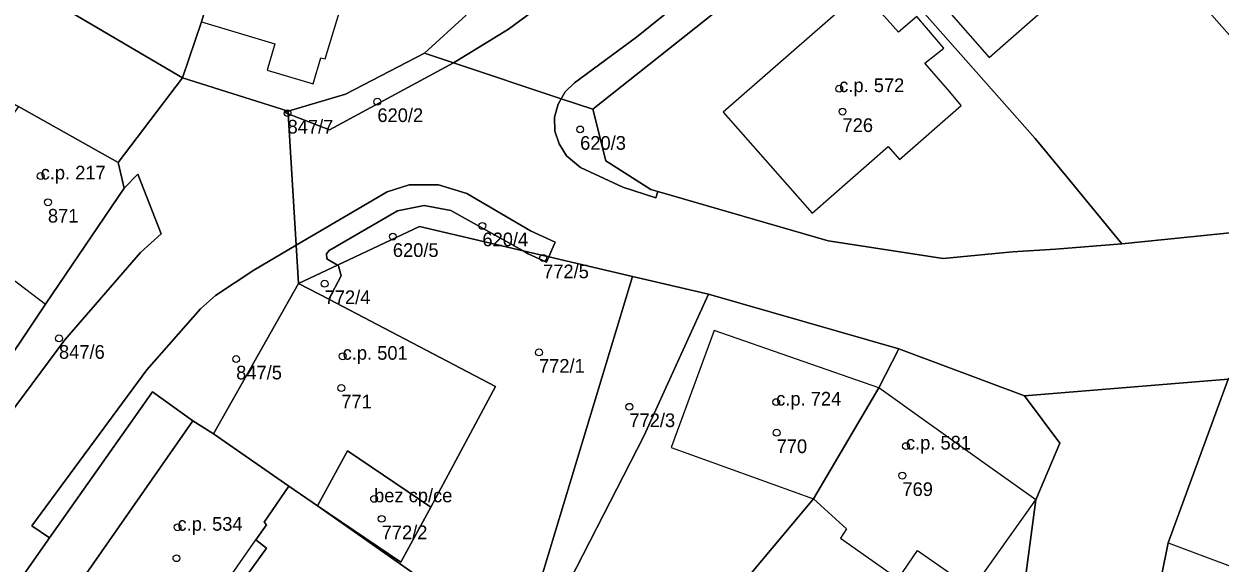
# Model space of a CAD drawing. Extents: x -878211 to -870363, y -1058464 to -1052522.
# Drawn here: x -874758 to -874670.5, y -1056517.4 to -1056478 of the extents above; entities that cross this region are included whole.
import ezdxf

# ---------------------------------------------------------------- set-up
doc = ezdxf.new("R2010")
doc.units = 0
for name, color, linetype in [('Definiční body', 7, 'Continuous'), ('Polygon budovy', 7, 'Continuous'), ('Polygon parcely', 7, 'Continuous')]:
    doc.layers.add(name, color=color, linetype=linetype)

msp = doc.modelspace()

# ---------------------------------------------------------------- linework, layer by layer
at = {"layer": 'Definiční body'}
for centre in [(-874698.4, -1056482.68994), (-874732.18, -1056483.63994), (-874698.16, -1056484.36994), (-874738.75, -1056484.47994), (-874717.35, -1056485.66994), (-874756.81, -1056489.07994), (-874756.28, -1056490.99994), (-874724.5, -1056492.72994), (-874731.05, -1056493.50994), (-874720.06, -1056495.06994), (-874736.04, -1056496.95994), (-874755.47, -1056500.95994), (-874742.51, -1056502.46994), (-874734.72, -1056502.26994), (-874720.36, -1056501.97994), (-874734.82, -1056504.58994), (-874713.75, -1056505.95994), (-874703.01, -1056505.61994), (-874702.98, -1056507.85994), (-874693.52, -1056508.83994), (-874693.78, -1056510.99994), (-874732.42, -1056512.69994), (-874731.87, -1056514.15994), (-874746.8, -1056514.77994), (-874746.88, -1056517.03994)]:
    msp.add_circle(centre, 0.25, dxfattribs=at)
at = {"layer": 'Polygon budovy'}
for points in [[(-874693.85, -1056473.06), (-874687.43, -1056480.41), (-874678.31, -1056472.38), (-874684.73, -1056465.04)], [(-874745.05, -1056477.8), (-874739.68, -1056479.4), (-874740.25, -1056481.34), (-874736.87, -1056482.34), (-874736.32, -1056480.43), (-874736.01, -1056480.5), (-874733.17, -1056471.2), (-874742.21, -1056468.41)], [(-874706.88, -1056484.4), (-874700.38, -1056491.8), (-874694.82, -1056486.91), (-874693.98, -1056487.87), (-874689.47, -1056483.92), (-874690.32, -1056482.93), (-874692.13, -1056480.82), (-874690.75, -1056479.72), (-874692.72, -1056477.42), (-874694.07, -1056478.56), (-874696.75, -1056475.52)], [(-874764.37, -1056492.43), (-874756.45, -1056498.46), (-874750.71, -1056489.97), (-874751.15, -1056488.09), (-874758.44, -1056484)], [(-874723.55, -1056504.49), (-874735.74, -1056498.1), (-874737.95, -1056496.94), (-874744.18, -1056507.93), (-874738.66, -1056511.77), (-874736.56, -1056513.22), (-874734.36, -1056509.18), (-874728.26, -1056513.3)], [(-874710.7, -1056508.95), (-874700.29, -1056512.7), (-874695.5, -1056504.57), (-874707.54, -1056500.37)], [(-874669.94, -1056503.95), (-874674.34, -1056515.92), (-874666.85, -1056518.73), (-874664.16, -1056511.46), (-874663.48, -1056512.85), (-874657.83, -1056512.22), (-874658.21, -1056508.8), (-874655.77, -1056508.33), (-874656.59, -1056501.1), (-874667.91, -1056502.32)], [(-874700.29, -1056512.7), (-874697.87, -1056514.9), (-874698.3, -1056515.58), (-874694.1, -1056518.54), (-874692.67, -1056516.47), (-874688.64, -1056519.27), (-874684.02, -1056512.77), (-874688.3, -1056509.72), (-874695.5, -1056504.57)], [(-874741.06, -1056515.69), (-874740.3, -1056514.6), (-874740.47, -1056514.4), (-874738.66, -1056511.77), (-874744.18, -1056507.93), (-874745.67, -1056507), (-874760.19, -1056527.76), (-874754.81, -1056531.56), (-874747.89, -1056521.57), (-874746.05, -1056522.85)], [(-874734.36, -1056509.18), (-874736.56, -1056513.22), (-874730.47, -1056517.32), (-874728.26, -1056513.3)]]:
    msp.add_lwpolyline(points, close=True, dxfattribs=at)
at = {"layer": 'Polygon parcely'}
for points in [[(-874663.52, -1056438.4), (-874672.43, -1056441.48), (-874672.5, -1056441.7), (-874673.54, -1056443), (-874674.2, -1056443.48), (-874682.75, -1056447.86), (-874689.17, -1056451.94), (-874695.4, -1056456.68), (-874715.47, -1056473.07), (-874722.59, -1056478.34), (-874726.37, -1056480.65), (-874726.62, -1056480.79), (-874718.74, -1056483.43), (-874718.45, -1056482.93), (-874717.77, -1056482.26), (-874713.22, -1056478.92), (-874687.75, -1056458.39), (-874684.49, -1056456.15), (-874678.51, -1056452.48), (-874674.25, -1056450.17), (-874670.55, -1056448.41), (-874665.5, -1056446.52)], [(-874665.5, -1056446.52), (-874670.55, -1056448.41), (-874674.25, -1056450.17), (-874678.51, -1056452.48), (-874684.49, -1056456.15), (-874687.75, -1056458.39), (-874713.22, -1056478.92), (-874717.77, -1056482.26), (-874718.45, -1056482.93), (-874718.74, -1056483.43), (-874716.43, -1056484.2), (-874698.53, -1056469.97), (-874686.86, -1056459.52), (-874673.94, -1056451.62), (-874671.18, -1056450.63), (-874653.34, -1056444.21)], [(-874725.69, -1056477.31), (-874728.74, -1056480.08), (-874726.62, -1056480.79), (-874726.37, -1056480.65), (-874722.59, -1056478.34), (-874715.47, -1056473.07)], [(-874658.14, -1056492.03), (-874672.92, -1056493.55), (-874677.72, -1056494.05), (-874682.57, -1056494.44), (-874685.72, -1056494.63), (-874690.79, -1056495.11), (-874699.2, -1056493.82), (-874711.67, -1056490.22), (-874711.81, -1056490.67), (-874714.23, -1056489.9), (-874717.32, -1056488.46), (-874718.34, -1056487.59), (-874718.89, -1056486.72), (-874719.21, -1056485.79), (-874719.22, -1056484.77), (-874718.97, -1056483.81), (-874718.74, -1056483.43), (-874726.62, -1056480.79), (-874735.69, -1056485.69), (-874738.7, -1056484.54)], [(-874763.27, -1056525.64), (-874756.17, -1056515.56), (-874757.46, -1056514.66), (-874749.04, -1056503.26), (-874745.11, -1056498.8), (-874744.03, -1056497.83), (-874741.22, -1056495.96), (-874738.12, -1056494.14), (-874738.7, -1056484.54), (-874738.95, -1056484.44), (-874738.71, -1056484.33), (-874746.43, -1056481.89), (-874751.15, -1056488.09), (-874750.71, -1056489.97), (-874749.7, -1056488.95), (-874747.99, -1056493.3), (-874749.51, -1056494.67), (-874755.04, -1056501.07), (-874762.73, -1056511.37), (-874764.42, -1056510.19), (-874768.48, -1056516.12), (-874775.04, -1056525.67)], [(-874738.7, -1056484.54), (-874738.12, -1056494.14), (-874731.47, -1056490.24), (-874729.85, -1056489.73), (-874727.7, -1056489.73), (-874725.63, -1056490.35), (-874720.98, -1056493.08), (-874719.18, -1056493.93), (-874719.64, -1056494.99), (-874713.52, -1056496.43), (-874707.96, -1056497.73), (-874694.05, -1056501.72), (-874684.86, -1056505.16), (-874669.94, -1056503.95)], [(-874675.79, -1056523.03), (-874674.34, -1056515.92), (-874669.94, -1056503.95), (-874684.86, -1056505.16), (-874682.26, -1056508.62), (-874684.02, -1056512.77), (-874685.26, -1056522.1)]]:
    msp.add_lwpolyline(points, dxfattribs=at)
for points in [[(-874746.43, -1056481.89), (-874754.95, -1056476.89), (-874763.22, -1056475.22), (-874774.43, -1056469.49), (-874777.11, -1056468.31), (-874792.6, -1056460.75), (-874795.75, -1056458.63), (-874796.48, -1056457.88), (-874796.08, -1056457.01), (-874799.5, -1056454.73), (-874803.79, -1056451.88), (-874813.86, -1056445.18), (-874811.44, -1056456.7), (-874804.76, -1056460.13), (-874796.2, -1056464.61), (-874787.26, -1056469.19), (-874780.67, -1056472.7), (-874779.11, -1056473.48), (-874770.31, -1056477.96), (-874761.17, -1056482.65), (-874758.44, -1056484), (-874751.15, -1056488.09)], [(-874745.05, -1056477.8), (-874742.21, -1056468.41), (-874744.75, -1056467.68), (-874743.73, -1056464.03), (-874742.87, -1056460.95), (-874753.3, -1056456.92), (-874756.19, -1056464.33), (-874757.22, -1056464.04), (-874758.27, -1056463.52), (-874762.27, -1056472.9), (-874763.22, -1056475.22), (-874754.95, -1056476.89), (-874746.43, -1056481.89)], [(-874686.86, -1056459.52), (-874698.53, -1056469.97), (-874684.07, -1056486.33), (-874681.76, -1056489.14), (-874677.72, -1056494.05), (-874672.92, -1056493.55), (-874658.14, -1056492.03), (-874671.51, -1056476.89)], [(-874738.71, -1056484.33), (-874734.51, -1056483.09), (-874728.74, -1056480.08), (-874725.69, -1056477.31), (-874726.52, -1056476.31), (-874731.9, -1056471.1), (-874732.33, -1056468.29), (-874741.48, -1056464.85), (-874743.73, -1056464.03), (-874744.75, -1056467.68), (-874742.21, -1056468.41), (-874745.05, -1056477.8), (-874746.43, -1056481.89)], [(-874712.17, -1056490.07), (-874711.67, -1056490.22), (-874699.2, -1056493.82), (-874690.79, -1056495.11), (-874685.72, -1056494.63), (-874682.57, -1056494.44), (-874677.72, -1056494.05), (-874681.76, -1056489.14), (-874684.07, -1056486.33), (-874698.53, -1056469.97), (-874716.43, -1056484.2), (-874715.48, -1056487.98)], [(-874650.8, -1056475.84), (-874654.76, -1056475.57), (-874662.19, -1056475.65), (-874666.67, -1056477.08), (-874667.61, -1056473.41), (-874671.51, -1056476.89), (-874658.14, -1056492.03), (-874651.63, -1056491.41), (-874651.42, -1056490.62), (-874650.75, -1056483.21), (-874651.15, -1056483.19)], [(-874738.71, -1056484.33), (-874738.7, -1056484.54), (-874735.69, -1056485.69), (-874726.62, -1056480.79), (-874728.74, -1056480.08), (-874734.51, -1056483.09)], [(-874756.45, -1056498.46), (-874750.71, -1056489.97), (-874751.15, -1056488.09), (-874758.44, -1056484), (-874761.17, -1056482.65), (-874766.12, -1056491.04), (-874765.94, -1056494.47), (-874768.7, -1056498.27), (-874767.89, -1056498.83), (-874766.17, -1056500.02), (-874760.51, -1056504.47)], [(-874718.74, -1056483.43), (-874718.97, -1056483.81), (-874719.22, -1056484.77), (-874719.21, -1056485.79), (-874718.89, -1056486.72), (-874718.34, -1056487.59), (-874717.32, -1056488.46), (-874714.23, -1056489.9), (-874711.81, -1056490.67), (-874711.67, -1056490.22), (-874712.17, -1056490.07), (-874715.48, -1056487.98), (-874716.43, -1056484.2)], [(-874738.7, -1056484.54), (-874738.71, -1056484.33), (-874738.95, -1056484.44)], [(-874760.51, -1056504.47), (-874764.42, -1056510.19), (-874762.73, -1056511.37), (-874755.04, -1056501.07), (-874749.51, -1056494.67), (-874747.99, -1056493.3), (-874749.7, -1056488.95), (-874750.71, -1056489.97), (-874756.45, -1056498.46)], [(-874735.1, -1056495.6), (-874735.87, -1056495.13), (-874735.9, -1056494.78), (-874735.72, -1056494.53), (-874730.7, -1056491.63), (-874728.76, -1056491.23), (-874726.8, -1056491.6), (-874721.53, -1056494.55), (-874719.64, -1056494.99), (-874719.18, -1056493.93), (-874720.98, -1056493.08), (-874725.63, -1056490.35), (-874727.7, -1056489.73), (-874729.85, -1056489.73), (-874731.47, -1056490.24), (-874738.12, -1056494.14), (-874737.95, -1056496.94)], [(-874735.1, -1056495.6), (-874729.09, -1056492.77), (-874721.53, -1056494.55), (-874726.8, -1056491.6), (-874728.76, -1056491.23), (-874730.7, -1056491.63), (-874735.72, -1056494.53), (-874735.9, -1056494.78), (-874735.87, -1056495.13)], [(-874721.15, -1056494.76), (-874721.53, -1056494.55), (-874729.09, -1056492.77), (-874735.1, -1056495.6), (-874735.02, -1056495.65), (-874734.82, -1056496.37), (-874735.74, -1056498.1), (-874723.55, -1056504.49), (-874728.26, -1056513.3), (-874730.47, -1056517.32), (-874736.56, -1056513.22), (-874725.57, -1056520.93), (-874721.37, -1056522.37), (-874713.52, -1056496.43), (-874719.64, -1056494.99), (-874719.81, -1056495.38)], [(-874737.95, -1056496.94), (-874738.12, -1056494.14), (-874741.22, -1056495.96), (-874744.03, -1056497.83), (-874745.11, -1056498.8), (-874749.04, -1056503.26), (-874757.46, -1056514.66), (-874756.17, -1056515.56), (-874748.64, -1056504.86), (-874745.67, -1056507), (-874744.18, -1056507.93)], [(-874719.81, -1056495.38), (-874719.64, -1056494.99), (-874721.53, -1056494.55), (-874721.15, -1056494.76)], [(-874737.95, -1056496.94), (-874735.74, -1056498.1), (-874734.82, -1056496.37), (-874735.02, -1056495.65), (-874735.1, -1056495.6)], [(-874707.96, -1056497.73), (-874713.52, -1056496.43), (-874721.37, -1056522.37), (-874720.15, -1056522.79), (-874719.59, -1056521.58), (-874712.68, -1056508.1)], [(-874737.95, -1056496.94), (-874744.18, -1056507.93), (-874738.66, -1056511.77), (-874736.56, -1056513.22), (-874734.36, -1056509.18), (-874728.26, -1056513.3), (-874723.55, -1056504.49), (-874735.74, -1056498.1)], [(-874707.96, -1056497.73), (-874712.68, -1056508.1), (-874719.59, -1056521.58), (-874720.15, -1056522.79), (-874721.31, -1056525.34), (-874718.3, -1056526.65), (-874716.44, -1056527.64), (-874713.87, -1056529.89), (-874704.82, -1056518.11), (-874700.29, -1056512.7), (-874695.5, -1056504.57), (-874694.05, -1056501.72)], [(-874669.94, -1056503.95), (-874674.34, -1056515.92), (-874675.79, -1056523.03), (-874648.58, -1056527.34), (-874649.03, -1056518.95), (-874649.23, -1056515.1), (-874649.31, -1056513.05), (-874650.24, -1056500.68), (-874653.13, -1056500.77), (-874656.59, -1056501.1), (-874667.91, -1056502.32)], [(-874688.12, -1056530.7), (-874685.26, -1056522.1), (-874684.02, -1056512.77), (-874682.26, -1056508.62), (-874684.86, -1056505.16), (-874694.05, -1056501.72), (-874695.5, -1056504.57), (-874700.29, -1056512.7), (-874704.82, -1056518.11), (-874701.37, -1056521.07), (-874699.33, -1056522.89), (-874697.32, -1056524.25)], [(-874756.17, -1056515.56), (-874763.27, -1056525.64), (-874769.01, -1056533.49), (-874765.98, -1056535.78), (-874760.19, -1056527.76), (-874745.67, -1056507), (-874748.64, -1056504.86)], [(-874745.67, -1056507), (-874760.19, -1056527.76), (-874765.98, -1056535.78), (-874758.76, -1056541.24), (-874749.93, -1056529.65), (-874740.3, -1056516.3), (-874741.06, -1056515.69), (-874740.3, -1056514.6), (-874740.47, -1056514.4), (-874738.66, -1056511.77), (-874744.18, -1056507.93)], [(-874736.56, -1056513.22), (-874730.47, -1056517.32), (-874728.26, -1056513.3), (-874734.36, -1056509.18)], [(-874723.49, -1056537.85), (-874716.44, -1056527.64), (-874718.3, -1056526.65), (-874721.31, -1056525.34), (-874720.15, -1056522.79), (-874721.37, -1056522.37), (-874725.57, -1056520.93), (-874736.56, -1056513.22), (-874738.66, -1056511.77), (-874740.47, -1056514.4), (-874740.3, -1056514.6), (-874741.06, -1056515.69), (-874740.3, -1056516.3), (-874749.93, -1056529.65), (-874746.56, -1056532.21), (-874740.28, -1056523.43), (-874732.01, -1056529.37), (-874738.3, -1056538.14), (-874728.64, -1056545.02)]]:
    msp.add_lwpolyline(points, close=True, dxfattribs=at)

# ---------------------------------------------------------------- texts
at = {"layer": 'Definiční body'}
for s, p in [('c.p. 572', (-874698.4, -1056482.94)), ('620/2', (-874732.18, -1056485.129)), ('847/7', (-874738.75, -1056485.969)), ('726', (-874698.16, -1056485.859)), ('620/3', (-874717.35, -1056487.159)), ('c.p. 217', (-874756.81, -1056489.33)), ('871', (-874756.28, -1056492.489)), ('620/4', (-874724.5, -1056494.219)), ('620/5', (-874731.05, -1056494.999)), ('772/5', (-874720.06, -1056496.559)), ('772/4', (-874736.04, -1056498.449)), ('847/6', (-874755.47, -1056502.449)), ('c.p. 501', (-874734.72, -1056502.52)), ('772/1', (-874720.36, -1056503.469)), ('847/5', (-874742.51, -1056503.959)), ('771', (-874734.82, -1056506.079)), ('c.p. 724', (-874703.01, -1056505.87)), ('772/3', (-874713.75, -1056507.449)), ('770', (-874702.98, -1056509.349)), ('c.p. 581', (-874693.52, -1056509.09)), ('bez cp/ce', (-874732.42, -1056512.95)), ('769', (-874693.78, -1056512.489)), ('c.p. 534', (-874746.8, -1056515.03)), ('772/2', (-874731.87, -1056515.649))]:
    msp.add_text(s, height=0.999996, dxfattribs=at).set_placement(p)

doc.saveas('drawing.dxf')
